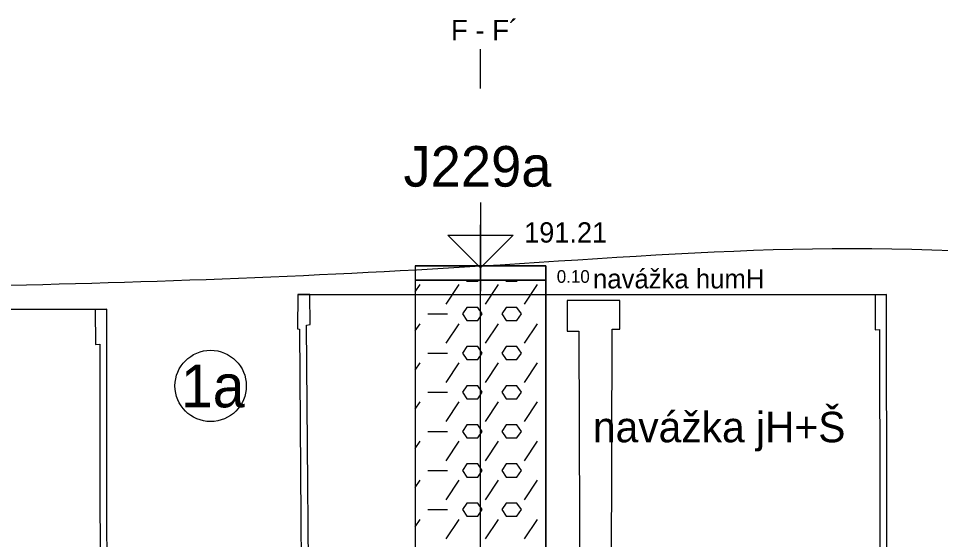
# Model space of a CAD drawing. Extents: x 3042 to 4120, y 576 to 2694.
# Drawn here: x 3405.34 to 3437.63, y 1868.13 to 1886.39 of the extents above; entities that cross this region are included whole.
import ezdxf

# ---------------------------------------------------------------- set-up
doc = ezdxf.new("R2010")
doc.units = 0
for name, color, linetype in [('15', 7, 'Continuous'), ('16', 7, 'Continuous'), ('17', 7, 'Continuous'), ('18', 7, 'Continuous'), ('22', 7, 'Continuous'), ('51', 7, 'Continuous'), ('52', 7, 'Continuous'), ('53', 7, 'Continuous'), ('56', 7, 'Continuous'), ('nádrže', 7, 'Continuous'), ('pomocna', 7, 'Continuous'), ('rozhraní', 7, 'Continuous')]:
    doc.layers.add(name, color=color, linetype=linetype)

msp = doc.modelspace()

# ---------------------------------------------------------------- linework, layer by layer
at = {"layer": '15'}
msp.add_lwpolyline([(3421.522, 1879.939), (3421.522, 1877.653), (3420.379, 1878.796), (3422.665, 1878.796), (3421.522, 1877.653)], dxfattribs=at)
at = {"layer": '18'}
msp.add_line((3421.522, 1832.717), (3421.522, 1877.717), dxfattribs=at)
at = {"layer": '22'}
msp.add_lwpolyline([(3421.522, 1883.939), (3421.522, 1883.939), (3421.522, 1885.308)], dxfattribs=at)
at = {"layer": '51'}
for p, q in [((3421.019, 1877.217), (3421.044, 1877.18)), ((3422.391, 1877.217), (3422.416, 1877.18)), ((3419.236, 1876.811), (3419.406, 1877.066)), ((3420.32, 1876.38), (3420.777, 1877.066)), ((3421.692, 1876.38), (3422.149, 1877.066)), ((3423.063, 1876.38), (3423.52, 1877.066)), ((3419.672, 1876.037), (3420.358, 1876.037)), ((3423.787, 1876.037), (3423.808, 1876.037)), ((3419.236, 1875.439), (3419.406, 1875.694)), ((3420.32, 1875.008), (3420.777, 1875.694)), ((3421.692, 1875.008), (3422.149, 1875.694)), ((3423.063, 1875.008), (3423.52, 1875.694)), ((3419.672, 1874.665), (3420.358, 1874.665)), ((3423.787, 1874.665), (3423.808, 1874.665)), ((3419.236, 1874.068), (3419.406, 1874.322)), ((3420.32, 1873.637), (3420.777, 1874.322)), ((3421.692, 1873.637), (3422.149, 1874.322)), ((3423.063, 1873.637), (3423.52, 1874.322)), ((3419.672, 1873.294), (3420.358, 1873.294)), ((3423.787, 1873.294), (3423.808, 1873.294)), ((3419.236, 1872.696), (3419.406, 1872.951)), ((3420.32, 1872.265), (3420.777, 1872.951)), ((3421.692, 1872.265), (3422.149, 1872.951)), ((3423.063, 1872.265), (3423.52, 1872.951)), ((3419.672, 1871.922), (3420.358, 1871.922)), ((3423.787, 1871.922), (3423.808, 1871.922)), ((3419.236, 1871.324), (3419.406, 1871.579)), ((3420.32, 1870.893), (3420.777, 1871.579)), ((3421.692, 1870.893), (3422.149, 1871.579)), ((3423.063, 1870.893), (3423.52, 1871.579)), ((3419.672, 1870.551), (3420.358, 1870.551)), ((3423.787, 1870.551), (3423.808, 1870.551)), ((3419.236, 1869.953), (3419.406, 1870.208)), ((3420.32, 1869.522), (3420.777, 1870.208)), ((3421.692, 1869.522), (3422.149, 1870.208)), ((3423.063, 1869.522), (3423.52, 1870.208)), ((3419.672, 1869.179), (3420.358, 1869.179)), ((3423.787, 1869.179), (3423.808, 1869.179)), ((3419.236, 1868.581), (3419.406, 1868.836)), ((3420.32, 1868.15), (3420.777, 1868.836)), ((3421.692, 1868.15), (3422.149, 1868.836)), ((3423.063, 1868.15), (3423.52, 1868.836))]:
    msp.add_line(p, q, dxfattribs=at)
for points in [[(3419.236, 1877.217), (3423.808, 1877.217), (3423.808, 1877.717), (3419.236, 1877.717)], [(3419.236, 1867.217), (3423.808, 1867.217), (3423.808, 1877.217), (3419.236, 1877.217)]]:
    msp.add_lwpolyline(points, close=True, dxfattribs=at)
for points in [[(3421.044, 1877.18), (3421.425, 1877.18), (3421.45, 1877.217)], [(3422.416, 1877.18), (3422.797, 1877.18), (3422.821, 1877.217)], [(3421.044, 1875.808), (3421.425, 1875.808), (3421.577, 1876.037), (3421.425, 1876.266), (3421.044, 1876.266), (3420.892, 1876.037), (3421.044, 1875.808)], [(3422.416, 1875.808), (3422.797, 1875.808), (3422.949, 1876.037), (3422.797, 1876.266), (3422.416, 1876.266), (3422.263, 1876.037), (3422.416, 1875.808)], [(3421.044, 1874.437), (3421.425, 1874.437), (3421.577, 1874.665), (3421.425, 1874.894), (3421.044, 1874.894), (3420.892, 1874.665), (3421.044, 1874.437)], [(3422.416, 1874.437), (3422.797, 1874.437), (3422.949, 1874.665), (3422.797, 1874.894), (3422.416, 1874.894), (3422.263, 1874.665), (3422.416, 1874.437)], [(3421.044, 1873.065), (3421.425, 1873.065), (3421.577, 1873.294), (3421.425, 1873.522), (3421.044, 1873.522), (3420.892, 1873.294), (3421.044, 1873.065)], [(3422.416, 1873.065), (3422.797, 1873.065), (3422.949, 1873.294), (3422.797, 1873.522), (3422.416, 1873.522), (3422.263, 1873.294), (3422.416, 1873.065)], [(3421.044, 1871.694), (3421.425, 1871.694), (3421.577, 1871.922), (3421.425, 1872.151), (3421.044, 1872.151), (3420.892, 1871.922), (3421.044, 1871.694)], [(3422.416, 1871.694), (3422.797, 1871.694), (3422.949, 1871.922), (3422.797, 1872.151), (3422.416, 1872.151), (3422.263, 1871.922), (3422.416, 1871.694)], [(3421.044, 1870.322), (3421.425, 1870.322), (3421.577, 1870.551), (3421.425, 1870.779), (3421.044, 1870.779), (3420.892, 1870.551), (3421.044, 1870.322)], [(3422.416, 1870.322), (3422.797, 1870.322), (3422.949, 1870.551), (3422.797, 1870.779), (3422.416, 1870.779), (3422.263, 1870.551), (3422.416, 1870.322)], [(3421.044, 1868.95), (3421.425, 1868.95), (3421.577, 1869.179), (3421.425, 1869.408), (3421.044, 1869.408), (3420.892, 1869.179), (3421.044, 1868.95)], [(3422.416, 1868.95), (3422.797, 1868.95), (3422.949, 1869.179), (3422.797, 1869.408), (3422.416, 1869.408), (3422.263, 1869.179), (3422.416, 1868.95)]]:
    msp.add_lwpolyline(points, dxfattribs=at)
at = {"layer": '53'}
for p, q in [((3419.236, 1877.717), (3423.808, 1877.717)), ((3419.236, 1877.717), (3419.236, 1832.717)), ((3423.808, 1877.717), (3423.808, 1832.717)), ((3419.236, 1877.217), (3423.808, 1877.217))]:
    msp.add_line(p, q, dxfattribs=at)
at = {"layer": '56'}
for p, q in [((3421.522, 1878.098), (3421.522, 1877.336)), ((3421.141, 1877.717), (3421.903, 1877.717)), ((3421.522, 1877.598), (3421.522, 1876.836)), ((3421.141, 1877.217), (3421.903, 1877.217))]:
    msp.add_line(p, q, dxfattribs=at)
at = {"layer": 'nádrže'}
for p, q in [((3415.124, 1876.717), (3435.744, 1876.717)), ((3387.809, 1876.2), (3408.429, 1876.2))]:
    msp.add_line(p, q, dxfattribs=at)
for points in [[(3415.527, 1863.072), (3415.425, 1875.636), (3415.549, 1875.661), (3415.544, 1876.717), (3415.124, 1876.717), (3415.114, 1875.512), (3415.179, 1875.498)], [(3426.084, 1858.398), (3426.128, 1875.497), (3426.399, 1875.497), (3426.395, 1876.51), (3424.551, 1876.51), (3424.554, 1875.435), (3424.96, 1875.435), (3425.019, 1858.606)], [(3435.762, 1860.445), (3435.744, 1876.717), (3435.343, 1876.706), (3435.345, 1875.484), (3435.499, 1875.488), (3435.512, 1862.936)], [(3400.049, 1854.375), (3406.301, 1856.531), (3406.256, 1859.816), (3408.446, 1859.928), (3408.429, 1876.2), (3408.028, 1876.189), (3408.03, 1874.967), (3408.184, 1874.971), (3408.197, 1862.419), (3405.542, 1861.903), (3405.571, 1858.185), (3405.439, 1858.16), (3405.437, 1858.417), (3398.987, 1855.952)], [(3415.179, 1875.498), (3415.285, 1860.595)]]:
    msp.add_lwpolyline(points, dxfattribs=at)
at = {"layer": 'pomocna'}
msp.add_line((3421.522, 1831.667), (3421.522, 1879.153), dxfattribs=at)
at = {"layer": 'rozhraní'}
msp.add_circle((3412.067, 1873.513), 1.25, dxfattribs=at)
msp.add_spline([(3236.452, 1878.417), (3239.095, 1877.105), (3239.244, 1877.105), (3286.672, 1877.617), (3328.072, 1877.067), (3356.302, 1877.217), (3384.922, 1876.917), (3421.522, 1877.717), (3443.804, 1877.717), (3445.36, 1877.717), (3446.602, 1878.817)], degree=3, dxfattribs=at)

# ---------------------------------------------------------------- texts
at = {"layer": '16'}
msp.add_text('J229a', height=1.4224, dxfattribs=at).set_placement((3418.823, 1880.496))
at = {"layer": '17'}
msp.add_text('191.21', height=0.7112, dxfattribs=at).set_placement((3423.046, 1878.535))
at = {"layer": '22'}
msp.add_text('F - F´', height=0.72, dxfattribs=at).set_placement((3420.486, 1885.618))
at = {"layer": '52'}
for s, height, p in [('0.10', 0.4445, (3424.189, 1877.125)), ('navážka humH', 0.6731, (3425.459, 1876.93)), ('navážka jH+Š', 1.0668, (3425.459, 1871.539))]:
    msp.add_text(s, height=height, dxfattribs=at).set_placement(p)
at = {"layer": 'rozhraní'}
msp.add_text('1a', height=1.5, dxfattribs=at).set_placement((3411.023, 1872.763))

doc.saveas('drawing.dxf')
